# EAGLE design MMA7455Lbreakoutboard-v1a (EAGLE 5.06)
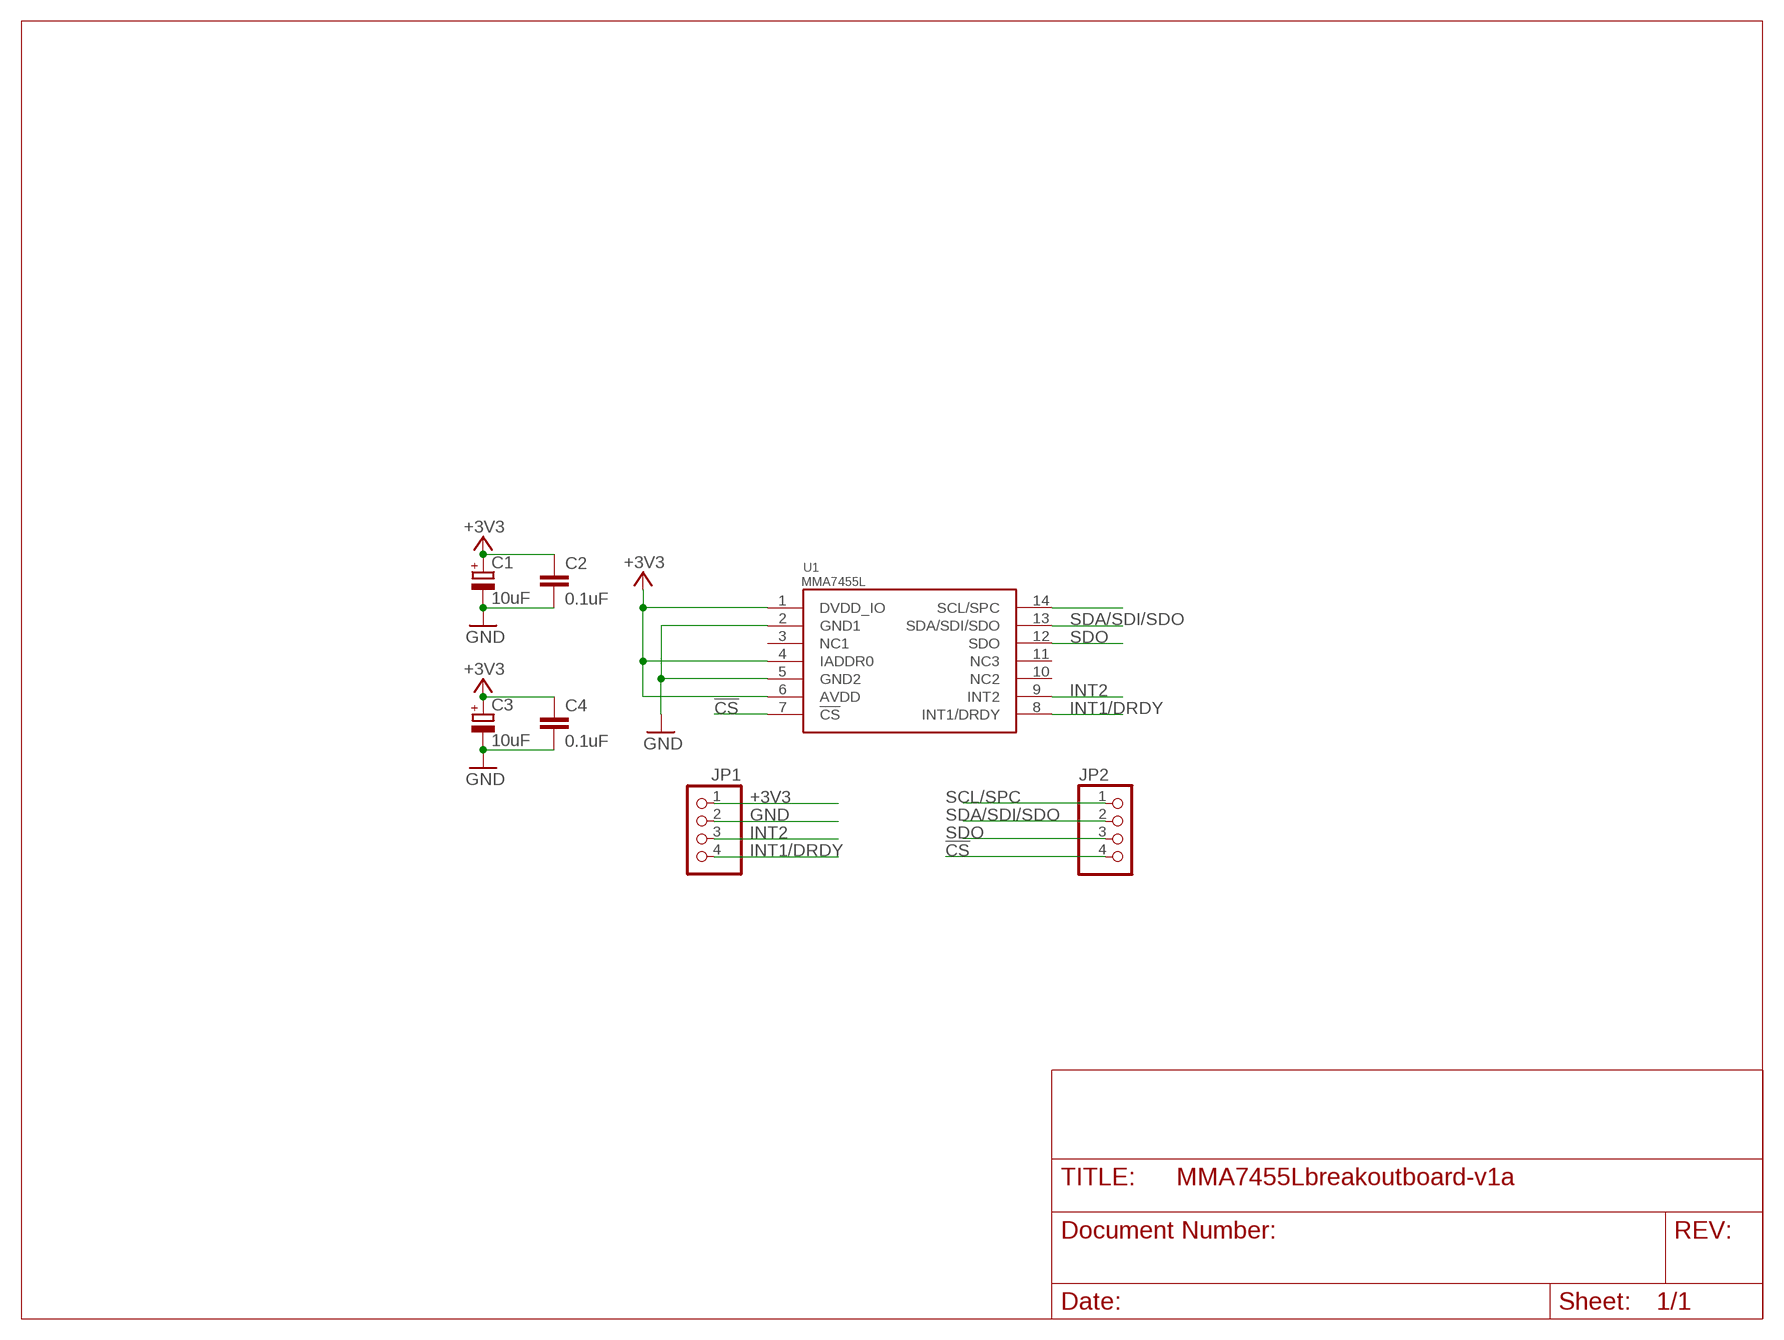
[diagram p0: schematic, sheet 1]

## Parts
C1  10uF  CAP_POLSMC_A  [SMC_A]
C2  0.1uF  CAPC805  [C805]
C3  10uF  CAP_POLSMC_A  [SMC_A]
C4  0.1uF  CAPC805  [C805]
JP1  PINHD-1X4  [1X04]
JP2  PINHD-1X4  [1X04]
U1  MMA7455L  [LGA-14]

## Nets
!CS: JP2.4 U1.7(!CS)
+3V3: C1.+ C2.1 C3.+ C4.1 JP1.1 U1.1(DVDD_IO) U1.4(IADDR0) U1.6(AVDD)
GND: C1.- C2.2 C3.- C4.2 JP1.2 U1.2(GND1) U1.5(GND2)
INT1/DRDY: JP1.4 U1.8(INT1/DRDY)
INT2: JP1.3 U1.9(INT2)
SCL/SPC: JP2.1 U1.14(SCL/SPC)
SDA/SDI/SDO: JP2.2 U1.13(SDA/SDI/SDO)
SDO: JP2.3 U1.12(SDO)
Unconnected: U1.3(NC1) U1.10(NC2) U1.11(NC3)

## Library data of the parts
C1 C3 = dp_devices:CAP_POL
C2 C4 = dp_devices:CAP
JP1 JP2 = pinhead - Copy:PINHD-1X4: PIN HEADER
U1 = jer_eagle:MMA7455L

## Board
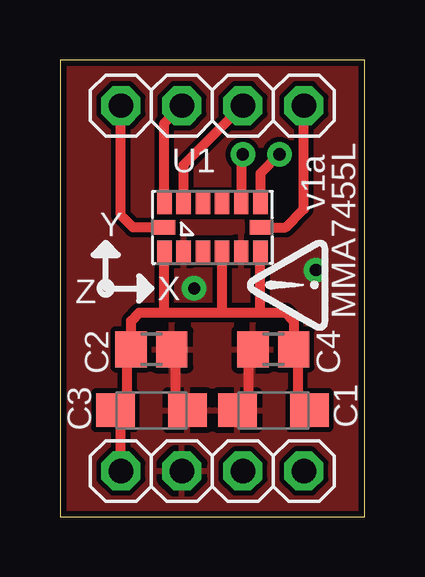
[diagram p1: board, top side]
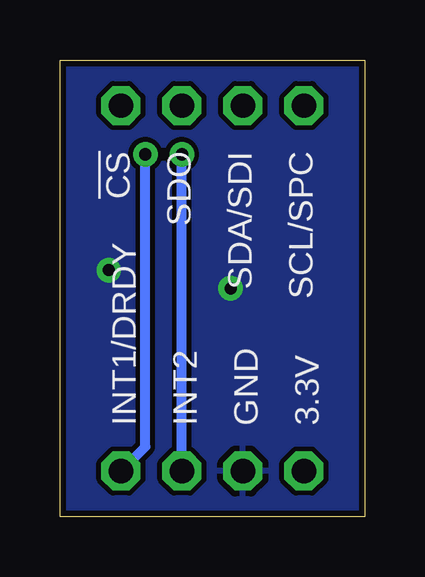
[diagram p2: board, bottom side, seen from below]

Size 12.7 x 19.05 mm. Coordinates in mm from the lower left corner, seen from the top.
Outline: 0,0 12.7,0 12.7,19.05 0,19.05 0,0
Copper layers (1*16): Top 0.035mm / dielectric 1.5mm / Bottom 0.035mm
Design rules "SparkFun- modified *": minimum track width 8mil, minimum drill 20mil, track to track 8mil, track to pad 8mil, pad to pad 6mil, via to via 8mil, smd to smd 6mil, copper to edge 10mil, drill to drill 8mil, minimum pad ring 12mil, minimum via ring 10mil, stop-mask expansion 2mil, vias tented up to drill 25mil, thermal gap 10mil

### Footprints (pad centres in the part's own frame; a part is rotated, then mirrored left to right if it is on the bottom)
SMC_A = smd 1.6 x 1.4: + -1.5,0; - 1.5,0
C805 = smd 1.3 x 1.5: 1 -0.85,0; 2 0.85,0
1X04 = drill 1.016 octagon: 1 -3.81,0; 2 -1.27,0; 3 1.27,0; 4 3.81,0
LGA-14 = smd 0.6 x 0.9: 1 -2,-1; 2 -1.2,-1; 3 -0.4,-1; 4 0.4,-1; 5 1.2,-1; 6 2,-1; 8 2,1; 9 1.2,1; 10 0.4,1; 11 -0.4,1; 12 -1.2,1; 13 -2,1 | smd 0.9 x 0.6: 7 2,0; 14 -2,0

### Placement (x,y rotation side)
C1  8.89,4.45 180 top
C2  3.81,6.99 0 top
C3  3.81,4.45 0 top
C4  8.89,6.99 180 top
JP1  6.35,1.91 0 top
JP2  6.35,17.14 0 top
U1  6.35,12.06 0 top
U$1  [DP_LOGO]  10.54,9.65 90 top

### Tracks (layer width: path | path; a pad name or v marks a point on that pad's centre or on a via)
!CS
  Top 0.406: U1.7 9.4,12.06 10.16,12.83 JP2.4
+3V3
  Top 0.406: C1.+ 9.91,4.93 9.91,6.99 C4.1 9.74,8.17 9.4,8.51 8.38,8.51 | JP1.1 2.54,4.21 C3.+ 2.79,4.93 2.79,6.99 C2.1 2.96,8.17 3.3,8.51 4.32,8.51 | 4.32,8.51 6.86,8.51 | 6.86,8.51 8.38,8.51 | U1.6 8.35,8.54 8.38,8.51 | U1.4 6.75,8.62 6.86,8.51 | U1.1 4.35,8.54 4.32,8.51
GND  (via drill 0.51)
  Top 0.406: C2.2 4.66,6.9 4.83,6.73 4.83,4.93 C3.- | C4.2 8.04,6.9 7.87,6.73 7.87,4.93 C1.-
  other vias: 5.59,9.53 10.67,10.29
  pour Bottom: 0,0 12.7,0 12.7,19.05 0,19.05
  pour Top: 0,0 12.7,0 12.7,19.05 0,19.05
INT1/DRDY  (via drill 0.51)
  Top 0.406: U1.8 8.35,14.32 v9.14,15.11
  Bottom 0.406: v9.14,15.11 9.14,2.92 JP1.4
INT2  (via drill 0.51)
  Top 0.406: U1.9 7.55,15.04 v7.62,15.11
  Bottom 0.406: JP1.3 v7.62,15.11
SCL/SPC
  Top 0.406: U1.14 3.05,12.06 2.54,12.57 JP2.1
SDA/SDI/SDO
  Top 0.406: U1.13 4.35,16.41 JP2.2
SDO
  Top 0.406: U1.12 5.15,14.68 JP2.3

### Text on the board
tNames: v1a | Y | Z | X | MMA7455L
bNames: SCL/SPC | SDA/SDI | SDO | !CS | 3.3V | GND | INT2 | INT1/DRDY
tDocu: MMA7455L Breakout Board v1a | Dangerous Prototypes | CC-0 | 2010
